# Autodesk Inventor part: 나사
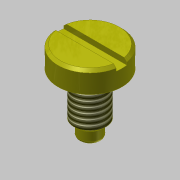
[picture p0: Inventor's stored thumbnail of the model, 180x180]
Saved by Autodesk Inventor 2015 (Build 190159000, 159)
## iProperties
Created: 2019-10
Part Number: 나사
Material: 스테인리스강
Document SubType Name: Modeling
Designer: mduedu
Density: 1 g/cm^3
Appearance: 노란색
Author: mduedu
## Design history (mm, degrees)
sketch "스케치1"
  geometry: L1 (0, 0)-(-6, 0); L2 (-6, 0)-(-6, -4); L3 (-6, -4)-(0, -4); L4 (0, -4)-(0, 0); L5 (0, -4)-(-3, -4); L6 (-3, -4)-(-3, -12.5); L7 (-3, -12.5)-(0, -12.5); L8 (0, -12.5)-(0, -4); L9 (0, -12.5)-(-2, -12.5); L10 (-2, -12.5)-(-2, -15); L11 (-2, -15)-(0, -15); L12 (0, -15)-(0, -12.5)
  constraints: 24 end point, 6 parallel, 3 horizontal, 3 perpendicular
  dimensions: "d0" = 15 distance between parallel lines of L11 L1; "d2" = 4 distance of L1.end L2.end; "d3" = 2.5 distance of L9.end L10.end; "d4" = 12 diameter of L2 L4; "d5" = 6 diameter of L6 L8; "d6" = 4 diameter of L10 L12
revolve "회전1" sketch "스케치1" stored, may be unused: angle "d7" = 90 deg
sketch "스케치2"
  geometry: L1 (2, -15)-(-2, -15) reference; L2 (-2, -15)-(-2, -12.5) reference; L3 (-2, -12.5)-(-3, -12.5) reference; L4 (-3, -12.5)-(-3, -4) reference; L5 (-3, -4)-(-6, -4) reference; L6 (-6, -4)-(-6, 0) reference; L7 (-6, 0)-(6, 0) reference; L8 (6, 0)-(6, -4) reference; L9 (6, -4)-(3, -4) reference; L10 (3, -4)-(3, -12.5) reference; L11 (3, -12.5)-(2, -12.5) reference; L12 (2, -12.5)-(2, -15) reference; L13 (0, 0)-(0, -15); L14 (-3, -4)-(-2.25, -4); L15 (-2.25, -4)-(-2.25, -4.5); L16 (-2.25, -4.5)-(-3, -4.5); L17 (-3, -4.5)-(-3, -4)
  constraints: 10 end point, 2 parallel, 1 horizontal, 1 midpoint, 1 perpendicular
  dimensions: "d8" = 4.5 diameter of L15 L13; "d10" = 0.5 distance between parallel lines of L16 L14
revolve "회전2" sketch "스케치2" stored, may be unused: angle "d11" = 90 deg
chamfer "모따기1" distance "d12" = 0.5; stored, may be unused: second distance "d13" = 2, angle "d14" = 45 deg
feature "스레드1" dims "d19" = 10, "d20" = 0
chamfer "모따기2" distance "d15" = 0.5; stored, may be unused: second distance "d16" = 2, angle "d17" = 45 deg
fillet "모깎기1" dims "d18" = 0.5
sketch "스케치3"
  geometry: L1 (-7.5, -1)-(7.5, -1); L2 (7.5, -1)-(7.5, 1); L3 (7.5, 1)-(-7.5, 1); L4 (-7.5, 1)-(-7.5, -1); L5 (-7.5, -1)-(7.5, 1); L6 (7.5, -1)-(-7.5, 1); 1 further point
  constraints: 12 end point, 2 midpoint, 2 parallel, 1 horizontal, 1 perpendicular
  dimensions: "d21" = 2 distance of L1.end L2.end; "d23" = 15 distance of L2.end L3.end
extrude "돌출1" cut sketch "스케치3" distance "d24" = 1; taper "d25" = 0 deg
node "솔리드1"
node "절단 모서리 투영1"
